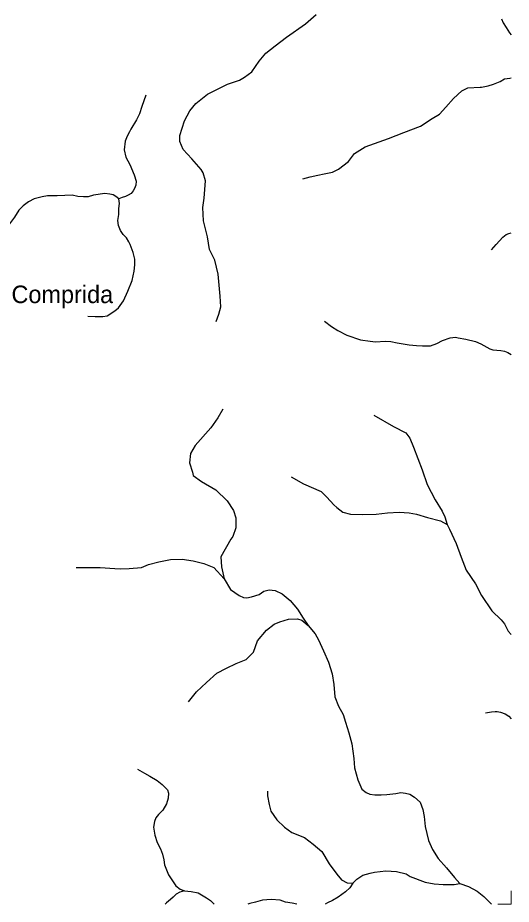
# Model space of a CAD drawing. Extents: x 436.3 to 500.4, y 8231 to 8286.4.
# Drawn here: x 495.5 to 500, y 8231.04 to 8239.13 of the extents above; entities that cross this region are included whole.
import ezdxf

# ---------------------------------------------------------------- set-up
doc = ezdxf.new("R2010")
doc.units = 0
doc.header["$LTSCALE"] = 0.08
doc.linetypes.add('LONG_DASHED', pattern=[7.5, 6, -1.5])
doc.layers.add('61', color=7, linetype='Continuous')
doc.layers.add('63', color=7, linetype='Continuous', lineweight=13)
doc.layers.add('9', color=7, linetype='LONG_DASHED', lineweight=25)

msp = doc.modelspace()

# ---------------------------------------------------------------- linework, layer by layer
at = {"layer": '63'}
msp.add_lwpolyline([(499.8768, 8231.0434), (500, 8231.0434), (500, 8231.1648)], dxfattribs=at)
at = {"layer": '9'}
msp.add_line((498.0446, 8231.0433), (498.0012, 8231.0524), dxfattribs=at)
for points in [[(497.3088, 8236.3616), (497.3332, 8236.4284), (497.3516, 8236.4952), (497.3455, 8236.5924), (497.3272, 8236.7928), (497.2966, 8236.9203), (497.2477, 8237.0174), (497.2294, 8237.1328), (497.1927, 8237.2784), (497.1867, 8237.3999), (497.1989, 8237.4848), (497.2112, 8237.6427), (497.1915, 8237.7184), (497.1731, 8237.7488), (497.0875, 8237.8459), (497.008, 8237.9308), (496.9774, 8238.0036), (496.9775, 8238.0582), (497.0204, 8238.1918), (497.0694, 8238.2829), (497.1245, 8238.3498), (497.2286, 8238.4349), (497.3143, 8238.4775), (497.4124, 8238.5263), (497.5226, 8238.5629), (497.5657, 8238.5892), (497.633, 8238.638), (497.7005, 8238.7353), (497.7617, 8238.8083), (497.8474, 8238.8754), (497.9514, 8238.9547), (498.1229, 8239.0767), (498.2208, 8239.1621)], [(499.9103, 8239.1221), (499.9266, 8239.0849), (499.9524, 8239.043), (499.9829, 8238.9942), (500, 8238.975)], [(499.7299, 8238.4992), (499.7881, 8238.51), (499.8374, 8238.5266), (499.8996, 8238.5498), (499.939, 8238.5747), (499.9884, 8238.5812), (500, 8238.5837)], [(498.1, 8237.663), (498.1649, 8237.6793), (498.2352, 8237.6955), (498.2947, 8237.7064), (498.3705, 8237.7226), (498.4247, 8237.7495), (498.5166, 8237.8196), (498.5707, 8237.8948), (498.668, 8237.9541), (498.879, 8238.0297), (499.0196, 8238.0837), (499.171, 8238.1432), (499.2792, 8238.2133), (499.3441, 8238.2511), (499.4036, 8238.3157), (499.4739, 8238.3965), (499.5496, 8238.4665), (499.6036, 8238.4936), (499.7171, 8238.4992), (499.7299, 8238.4992)], [(496.6672, 8238.4248), (496.6296, 8238.3235), (496.6092, 8238.2559), (496.5819, 8238.202), (496.5308, 8238.1166), (496.5171, 8238.0896), (496.4967, 8238.0524), (496.4796, 8238.0052), (496.4693, 8237.9275), (496.4863, 8237.86), (496.5203, 8237.7924), (496.561, 8237.6979), (496.578, 8237.6406), (496.5746, 8237.6034), (496.5644, 8237.573), (496.5507, 8237.5528), (496.5337, 8237.5292), (496.5064, 8237.5123), (496.4826, 8237.5022), (496.4522, 8237.4933), (496.4212, 8237.4803)], [(496.4212, 8237.4803), (496.3951, 8237.5015), (496.3688, 8237.515), (496.3387, 8237.5228), (496.2928, 8237.5294), (496.191, 8237.5131), (496.1418, 8237.4969), (496.0991, 8237.4969), (496.0467, 8237.5002), (495.9942, 8237.5133), (495.9285, 8237.5101), (495.8597, 8237.507), (495.7707, 8237.5068), (495.7215, 8237.4971), (495.6493, 8237.481), (495.5967, 8237.4518), (495.5476, 8237.4161), (495.5082, 8237.3771), (495.4687, 8237.312), (495.4228, 8237.2503), (495.3997, 8237.2114), (495.3768, 8237.1854), (495.357, 8237.1691), (495.3302, 8237.1297)], [(496.1382, 8236.4092), (496.2039, 8236.4058), (496.2761, 8236.4058), (496.3154, 8236.4123), (496.3844, 8236.4578), (496.4172, 8236.4838), (496.4631, 8236.5489), (496.5026, 8236.6368), (496.5421, 8236.7344), (496.5618, 8236.819), (496.5684, 8236.8784), (496.5684, 8236.9305), (496.552, 8236.9891), (496.5258, 8237.0639), (496.5134, 8237.087), (496.4898, 8237.1225), (496.4603, 8237.155), (496.4373, 8237.1908), (496.4177, 8237.2364), (496.4111, 8237.2819), (496.4211, 8237.3372), (496.4211, 8237.3925), (496.4277, 8237.438), (496.4212, 8237.4803)], [(499.8188, 8237.0158), (499.8609, 8237.064), (499.9225, 8237.1292), (499.9542, 8237.1537), (499.9772, 8237.1645), (500, 8237.1686)], [(498.2956, 8236.3624), (498.3618, 8236.3139), (498.4195, 8236.2778), (498.5015, 8236.2357), (498.6261, 8236.1936), (498.7142, 8236.1817), (498.7628, 8236.1758), (498.8509, 8236.1818), (498.9025, 8236.1789), (498.9602, 8236.1669), (499.0695, 8236.1489), (499.1363, 8236.143), (499.191, 8236.137), (499.2638, 8236.1371), (499.3215, 8236.1613), (499.3731, 8236.1886), (499.443, 8236.2128), (499.4923, 8236.2186), (499.5166, 8236.2126), (499.5864, 8236.2006), (499.6745, 8236.1766), (499.7231, 8236.1555), (499.8051, 8236.1104), (499.8325, 8236.1013), (499.8688, 8236.0984), (499.9053, 8236.0954), (499.9386, 8236.0894), (499.969, 8236.0773), (500, 8236.0591)], [(497.3687, 8235.56), (497.3228, 8235.4804), (497.2596, 8235.3893), (497.1162, 8235.2299), (497.0761, 8235.1559), (497.0646, 8235.0705), (497.0933, 8234.985), (497.099, 8234.9565), (497.1737, 8234.8995), (497.3056, 8234.8254), (497.409, 8234.7228), (497.4663, 8234.6373), (497.4893, 8234.5689), (497.4893, 8234.4776), (497.4607, 8234.3978), (497.4435, 8234.3751), (497.3519, 8234.2134), (497.3577, 8234.1221), (497.3807, 8234.0137)], [(498.7459, 8235.5048), (498.9246, 8235.4024), (499.0396, 8235.3434), (499.0753, 8235.296), (499.1071, 8235.2133), (499.1865, 8235.0082), (499.2342, 8234.874), (499.3057, 8234.732), (499.3692, 8234.6293), (499.3931, 8234.578), (499.4169, 8234.5069)], [(497.9927, 8234.9431), (498.1038, 8234.8801), (498.2665, 8234.8091), (498.3181, 8234.7578), (498.3816, 8234.6868), (498.4094, 8234.6631), (498.465, 8234.6197), (498.5324, 8234.6039), (498.6396, 8234.5999), (498.7666, 8234.6039), (498.8698, 8234.6156), (498.9769, 8234.6196), (499.0681, 8234.6156), (499.1356, 8234.6038), (499.2348, 8234.5721), (499.3538, 8234.5406), (499.4169, 8234.5069)], [(499.4169, 8234.5069), (499.4372, 8234.4656), (499.4968, 8234.3353), (499.5445, 8234.2089), (499.5883, 8234.0903), (499.673, 8233.9666), (499.7286, 8233.86), (499.8239, 8233.7216), (499.9074, 8233.6385), (499.9391, 8233.603), (499.9709, 8233.5357), (500, 8233.5044)], [(496.0323, 8234.1161), (496.1321, 8234.1159), (496.2511, 8234.1158), (496.3853, 8234.108), (496.4391, 8234.1041), (496.5159, 8234.1079), (496.6272, 8234.1153), (496.6924, 8234.1419), (496.7846, 8234.1685), (496.892, 8234.1875), (496.9995, 8234.1912), (497.0993, 8234.1759), (497.1954, 8234.1528), (497.2875, 8234.1145), (497.3807, 8234.0137)], [(497.3807, 8234.0137), (497.4381, 8233.9167), (497.5185, 8233.8597), (497.5583, 8233.8434), (497.5891, 8233.8404), (497.6321, 8233.8494), (497.6997, 8233.8708), (497.7428, 8233.9013), (497.792, 8233.9135), (497.8474, 8233.9074), (497.912, 8233.8767), (497.9828, 8233.8154), (498.0504, 8233.7359), (498.1028, 8233.6532), (498.149, 8233.5859)], [(497.0562, 8232.8907), (497.1297, 8232.9822), (497.2218, 8233.0674), (497.3137, 8233.1528), (497.4027, 8233.1985), (497.4917, 8233.2411), (497.5808, 8233.2775), (497.6482, 8233.3446), (497.685, 8233.4454), (497.7678, 8233.5428), (497.8384, 8233.5977), (497.8906, 8233.619), (497.9673, 8233.6434), (498.0502, 8233.6464), (498.0901, 8233.634), (498.149, 8233.5859)], [(498.149, 8233.5859), (498.2106, 8233.5093), (498.2414, 8233.4573), (498.2881, 8233.3549), (498.3344, 8233.2508), (498.3652, 8233.1467), (498.3807, 8233.0488), (498.3901, 8232.9355), (498.424, 8232.8498), (498.4672, 8232.7732), (498.4891, 8232.7039), (498.52, 8232.6089), (498.5447, 8232.5079), (498.5634, 8232.373), (498.5696, 8232.2873), (498.6006, 8232.1801), (498.6376, 8232.0943), (498.6777, 8232.0635), (498.7095, 8232.0465), (498.7556, 8232.0403), (498.8141, 8232.0402), (498.8663, 8232.0462), (498.9463, 8232.0553), (498.9924, 8232.0644), (499.0354, 8232.0581), (499.0755, 8232.0488), (499.1186, 8232.0213), (499.1678, 8231.9752), (499.1926, 8231.9078), (499.205, 8231.8434), (499.2144, 8231.7515), (499.2453, 8231.6258), (499.2824, 8231.543), (499.3348, 8231.4602), (499.4087, 8231.3743), (499.4827, 8231.2884), (499.5319, 8231.2331)], [(499.7665, 8232.7905), (499.8203, 8232.799), (499.8526, 8232.8011), (499.8719, 8232.8033), (499.9021, 8232.7946), (499.9451, 8232.7817), (499.9774, 8232.7582), (500, 8232.7339)], [(496.5909, 8232.2763), (496.6546, 8232.2396), (496.7037, 8232.2127), (496.77, 8232.1711), (496.8166, 8232.1368), (496.8657, 8232.0879), (496.8731, 8232.0561), (496.8707, 8232.0098), (496.8561, 8231.9611), (496.8219, 8231.9025), (496.7827, 8231.8627), (496.7583, 8231.8311), (496.746, 8231.7993), (496.7363, 8231.7481), (496.7488, 8231.6725), (496.771, 8231.6065), (496.8005, 8231.5478), (496.8202, 8231.5), (496.8327, 8231.4487), (496.8376, 8231.4024), (496.8549, 8231.3584), (496.8746, 8231.3119), (496.9091, 8231.2557), (496.941, 8231.2118), (496.9803, 8231.1824), (497.0204, 8231.1646)], [(497.7761, 8232.0759), (497.7762, 8232.0331), (497.7917, 8231.9534), (497.8071, 8231.8921), (497.8627, 8231.8123), (497.9305, 8231.7479), (497.9982, 8231.6988), (498.1151, 8231.6526), (498.1922, 8231.5911), (498.2723, 8231.5236), (498.3402, 8231.4132), (498.408, 8231.3181), (498.4511, 8231.2659), (498.5035, 8231.2382), (498.5557, 8231.235)], [(498.5557, 8231.235), (498.5926, 8231.2737), (498.6449, 8231.3073), (498.7125, 8231.3255), (498.7525, 8231.3376), (498.857, 8231.3497), (498.9524, 8231.3433), (499.0416, 8231.3217), (499.0785, 8231.2971), (499.2153, 8231.2445), (499.2984, 8231.229), (499.3784, 8231.2227), (499.4799, 8231.2225), (499.5319, 8231.2331)], [(498.5557, 8231.235), (498.5267, 8231.1944), (498.4886, 8231.1555), (498.421, 8231.1069), (498.3703, 8231.0764), (498.3234, 8231.0553), (498.303, 8231.0434)], [(499.5319, 8231.2331), (499.609, 8231.2039), (499.6891, 8231.164), (499.7506, 8231.1148), (499.8122, 8231.0505), (499.8186, 8231.0434)], [(497.0204, 8231.1646), (496.9763, 8231.1549), (496.9445, 8231.1354), (496.9176, 8231.1087), (496.8907, 8231.0867), (496.8565, 8231.0575), (496.843, 8231.0432)], [(497.0204, 8231.1646), (497.0817, 8231.1596), (497.1455, 8231.1472), (497.2216, 8231.1006), (497.2577, 8231.0761), (497.2909, 8231.0433)], [(498.0012, 8231.0524), (497.9423, 8231.0623), (497.8933, 8231.0796), (497.8098, 8231.087), (497.7315, 8231.0799), (497.6678, 8231.063), (497.6163, 8231.0509), (497.5977, 8231.0433)]]:
    msp.add_lwpolyline(points, dxfattribs=at)

# ---------------------------------------------------------------- texts
at = {"layer": '61'}
msp.add_text('Lagoa Comprida', height=0.16, dxfattribs=at).set_placement((494.7874, 8236.5283))

doc.saveas('drawing.dxf')
